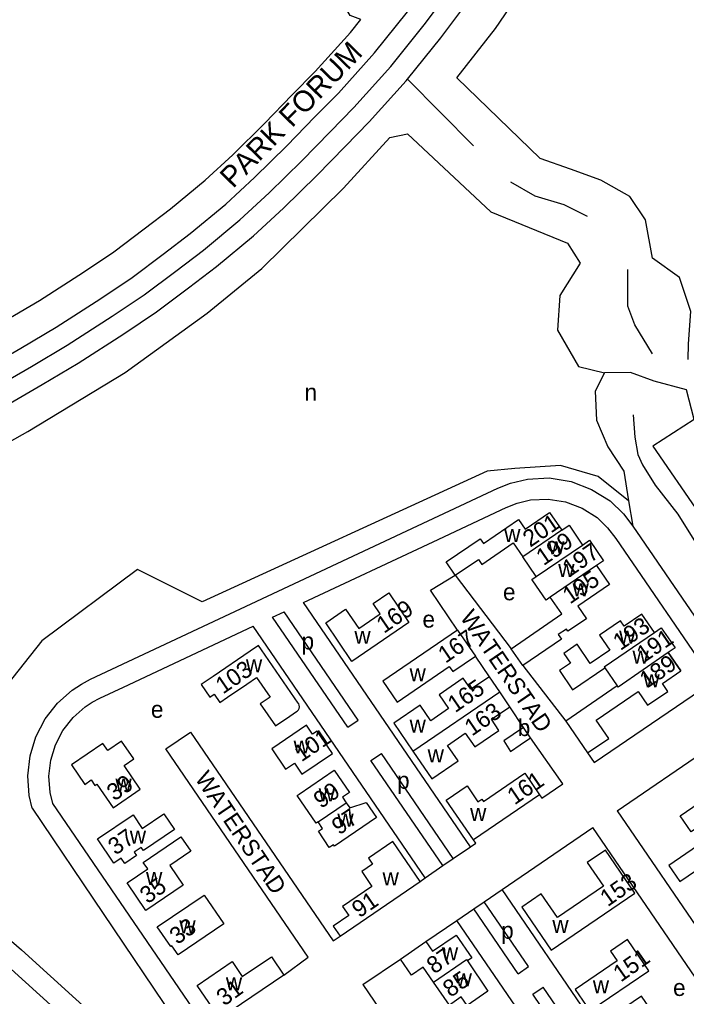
# Model space of a CAD drawing. Extents: x 154320 to 156262, y 382651 to 384180.
# Drawn here: x 155553.7 to 155711.8, y 383414.4 to 383646 of the extents above; entities that cross this region are included whole.
import ezdxf

# ---------------------------------------------------------------- set-up
doc = ezdxf.new("R2010")
doc.units = 0
for name, color, linetype in [('BLT_Basislijn', 7, 'Continuous'), ('BLT_Bebouwing', 7, 'Continuous'), ('BLT_Centroide', 7, 'Continuous'), ('BLT_Huisnummer', 7, 'Continuous'), ('BLT_Huisnummer_ tussenligend', 7, 'Continuous'), ('BLT_Onderverdeling_panden', 7, 'Continuous'), ('BLT_Straatnaam', 7, 'Continuous')]:
    doc.layers.add(name, color=color, linetype=linetype)

msp = doc.modelspace()

# ---------------------------------------------------------------- linework, layer by layer
at = {"layer": 'BLT_Basislijn'}
for p, q in [((155645.33, 383631.5), (155645.63, 383631.87)), ((155661.26, 383616.07), (155645.63, 383631.87)), ((155698.05, 383531.88), (155699.07, 383525.89)), ((155621, 383507.76), (155651.71, 383522.17)), ((155656.99, 383514.23), (155670.22, 383496.83)), ((155660.56, 383449.87), (155621, 383507.76)), ((155613.66, 383504.31), (155616.41, 383505.6)), ((155633.98, 383479.9), (155616.41, 383505.6)), ((155631.5, 383478.2), (155613.66, 383504.31)), ((155578.35, 383487.74), (155609.08, 383502.16)), ((155649.86, 383442.48), (155609.08, 383502.16)), ((155665.08, 383490.18), (155661.77, 383495.05)), ((155672.99, 383492.8), (155683.16, 383479.67)), ((155689.88, 383469.84), (155718.17, 383489.1)), ((155673.16, 383478.16), (155669.95, 383483.07)), ((155631.5, 383478.2), (155633.98, 383479.9)), ((155695.34, 383458.35), (155725.22, 383478.78)), ((155682.46, 383464.79), (155674.81, 383475.7)), ((155636.98, 383470.3), (155639.45, 383471.99)), ((155656.47, 383447.09), (155639.45, 383471.99)), ((155688.35, 383472.09), (155689.88, 383469.84)), ((155653.99, 383445.41), (155636.98, 383470.3)), ((155556.64, 383458.99), (155593.76, 383404.06)), ((155695.34, 383458.35), (155746.12, 383384.05)), ((155668.08, 383439.72), (155689.56, 383454.4)), ((155736.8, 383385.3), (155689.56, 383454.4)), ((155656.47, 383447.09), (155660.56, 383449.87)), ((155649.86, 383442.48), (155653.99, 383445.41)), ((155653.99, 383445.41), (155656.47, 383447.09)), ((155648.65, 383441.62), (155649.86, 383442.48)), ((155663.84, 383436.82), (155668.08, 383439.72)), ((155718.85, 383365.44), (155668.08, 383439.72)), ((155661.36, 383435.13), (155663.84, 383436.82)), ((155674.33, 383421.45), (155663.84, 383436.82)), ((155657.35, 383432.39), (155661.36, 383435.13)), ((155671.92, 383419.68), (155661.36, 383435.13)), ((155649.99, 383427.35), (155657.35, 383432.39)), ((155708.13, 383358.08), (155657.35, 383432.39)), ((155627.99, 383427.51), (155629.65, 383428.63)), ((155616.31, 383419.44), (155622.12, 383423.7)), ((155635.07, 383417.16), (155643.96, 383423.23)), ((155671.92, 383419.68), (155674.33, 383421.45)), ((155635.07, 383417.16), (155685.86, 383342.86)), ((155675.38, 383414.87), (155677.85, 383416.57)), ((155692.79, 383389.39), (155675.38, 383414.87)), ((155695.26, 383391.09), (155677.85, 383416.57))]:
    msp.add_line(p, q, dxfattribs=at)
for points in [[(155634.56, 383646.03), (155632.06, 383646.95), (155621.94, 383663.64), (155608.88, 383712.13), (155584.78, 383742.91), (155588.99, 383764.63), (155578.77, 383762.24), (155550.55, 383734.97), (155547.89, 383720.5), (155553.04, 383704.86), (155548.1, 383677.23), (155536.76, 383648.78), (155496.98, 383683.49), (155480.24, 383672.06), (155468.97, 383655.07), (155453.89, 383625.83), (155444.31, 383633.22), (155434.65, 383632.62), (155423.38, 383626.53), (155417.9, 383619.16), (155415.76, 383606.74), (155415.92, 383588.66), (155411.04, 383581.59)], [(155645.63, 383631.87), (155653.52, 383641.7), (155660.18, 383650.53), (155667.6, 383661.59), (155674.2, 383671.69), (155680.39, 383682.59), (155686.27, 383693.88), (155690.18, 383702.32), (155694.04, 383711.19), (155696.16, 383716.29)], [(155657.33, 383632.2), (155666.55, 383643.87), (155679.77, 383663.41), (155688.85, 383680.58), (155694.77, 383694.59), (155698.64, 383702.82)], [(155473.87, 383522.91), (155483.71, 383526.69), (155493.7, 383530.96), (155504.83, 383536.09), (155512.64, 383539.82), (155524.25, 383545.7), (155533.73, 383550.62), (155542.77, 383555.83), (155556.5, 383563.77), (155564.94, 383568.79), (155575.66, 383575.68), (155583.25, 383580.77), (155590.73, 383586.39), (155597.25, 383591.37), (155605.88, 383598.5), (155612.82, 383604.92), (155620.6, 383612.55), (155627.28, 383619.42), (155632.9, 383625.15), (155641.67, 383634.9), (155649.57, 383644.77), (155656.1, 383653.43)], [(155540.27, 383560.16), (155553.97, 383568.09), (155562.31, 383573.04), (155572.92, 383579.86), (155580.35, 383584.85), (155587.71, 383590.38), (155594.14, 383595.29), (155602.59, 383602.27), (155609.37, 383608.54), (155617.06, 383616.08), (155623.7, 383622.92), (155629.26, 383628.58), (155637.85, 383638.14), (155645.62, 383647.83)], [(155549, 383573.88), (155550.17, 383574.56), (155558.37, 383579.42), (155568.8, 383586.13), (155576, 383590.96), (155583.18, 383596.36), (155589.47, 383601.17), (155597.65, 383607.92), (155604.2, 383613.97), (155611.74, 383621.37), (155618.33, 383628.15), (155623.79, 383633.72), (155632.13, 383642.99), (155634.56, 383646.03)], [(155481.78, 383520.59), (155485.59, 383522.05), (155495.73, 383526.39), (155506.95, 383531.57), (155514.85, 383535.33), (155526.53, 383541.25), (155536.13, 383546.23), (155545.27, 383551.5), (155559.03, 383559.46), (155567.57, 383564.53), (155578.41, 383571.5), (155586.14, 383576.69), (155593.74, 383582.41), (155600.36, 383587.46), (155609.17, 383594.73), (155616.27, 383601.3), (155624.15, 383609.02), (155630.85, 383615.93), (155636.55, 383621.73), (155645.33, 383631.5)], [(155712.22, 383565.38), (155712.25, 383569.11), (155712.86, 383576.76), (155710.15, 383584.83), (155703.72, 383589.45), (155702.06, 383598.56), (155698.39, 383604.03), (155691.52, 383607.97), (155684.3, 383610.54), (155677.08, 383613.11), (155657.33, 383632.2)], [(155484.43, 383512.94), (155506.14, 383522.26), (155534.38, 383536.42), (155555.63, 383548.36), (155578.72, 383562.32), (155598.15, 383576.38), (155611.08, 383587.01), (155630.5, 383606.01), (155641.48, 383618.06), (155645.65, 383618.9)], [(155645.65, 383618.9), (155665.38, 383600.45), (155683.59, 383592.96), (155686.58, 383588.23), (155681.79, 383580.61), (155681.2, 383572.34), (155686.23, 383563.75), (155692.32, 383562.27)], [(155688.31, 383599.28), (155682.79, 383602.12), (155675.91, 383604.17), (155670.14, 383607.44)], [(155703.77, 383566.76), (155699.56, 383573.65), (155697.9, 383578.05), (155697.9, 383586.74)], [(155692.32, 383562.27), (155690.15, 383557.87), (155690.5, 383551.02), (155693.18, 383544.69), (155696.96, 383538.96), (155698.05, 383531.88)], [(155713.63, 383551.16), (155711.84, 383558.19), (155704.16, 383560.3), (155698.52, 383562.36), (155692.32, 383562.27)], [(155699.18, 383552.32), (155699.56, 383547.02), (155700.26, 383542.84), (155701.35, 383540.44), (155704.4, 383535.59), (155709.75, 383528.69), (155713.91, 383522), (155717.27, 383515.75), (155720.43, 383507.15), (155722.7, 383502.36), (155724.5, 383499.1)], [(155713.63, 383551.16), (155703.82, 383544.84), (155736.76, 383496.93)], [(155698.05, 383531.88), (155690.89, 383537.69), (155681.93, 383540.29), (155671.11, 383539.57), (155664.57, 383538.95), (155596.99, 383507.93), (155581.65, 383515.6), (155558.93, 383498.71), (155544.8, 383480.89), (155542.65, 383466.76)], [(155559.74, 383480.18), (155562.69, 383483.92), (155566.16, 383486.99), (155568.32, 383488.41), (155570.47, 383489.56), (155667.03, 383534.88), (155670.11, 383536.1), (155674.1, 383537.06), (155679.27, 383537.32), (155684.46, 383536.51), (155689.3, 383534.61), (155693.73, 383531.87), (155696.83, 383528.82), (155699.07, 383525.89)], [(155651.71, 383522.17), (155669.01, 383530.29), (155671.62, 383531.32), (155674.82, 383532.09), (155679.01, 383532.3), (155683.15, 383531.66), (155687.05, 383530.13), (155690.62, 383527.92), (155693.07, 383525.51), (155695.02, 383522.96), (155718.17, 383489.1)], [(155699.07, 383525.89), (155721.42, 383493.2)], [(155473.87, 383522.91), (155483.98, 383497.86), (155486.36, 383493.38), (155496.62, 383477.01), (155506.99, 383465.16), (155518.91, 383453.74), (155544.48, 383433.68), (155554.14, 383425.4), (155573.89, 383407.44), (155578.88, 383402.26), (155583.05, 383396.74)], [(155657.54, 383501.24), (155651.07, 383510.7), (155656.99, 383514.23)], [(155561.52, 383460.08), (155560.92, 383462.75), (155560.63, 383466.57), (155561.08, 383470.38), (155562.2, 383474.05), (155563.96, 383477.46), (155566.34, 383480.47), (155569.21, 383483.01), (155570.88, 383484.11), (155572.72, 383485.1), (155578.35, 383487.74)], [(155556.64, 383458.99), (155555.96, 383462.01), (155555.61, 383466.68), (155556.17, 383471.41), (155557.55, 383475.94), (155559.74, 383480.18)], [(155588.38, 383473.06), (155594.16, 383477.01), (155627.99, 383427.51)], [(155622.12, 383423.7), (155588.38, 383473.06)], [(155676.94, 383462.17), (155677.47, 383461.39), (155682.46, 383464.79)], [(155597.88, 383406.88), (155561.52, 383460.08)], [(155660.56, 383449.87), (155661.82, 383450.73), (155661.29, 383451.5)], [(155541.74, 383429.44), (155550.83, 383421.65), (155570.4, 383403.86), (155575.07, 383399.01), (155578.92, 383393.92)]]:
    msp.add_lwpolyline(points, dxfattribs=at)
at = {"layer": 'BLT_Bebouwing'}
for p, q in [((155676.18, 383513.95), (155673, 383518.59)), ((155657.54, 383501.24), (155661.77, 383495.05)), ((155610.34, 383497.6), (155608.35, 383496.24)), ((155672.99, 383492.8), (155670.22, 383496.83)), ((155707.48, 383495.9), (155710.43, 383491.56)), ((155692.46, 383492.29), (155695.37, 383488.03)), ((155667.52, 383486.62), (155665.08, 383490.18)), ((155669.95, 383483.07), (155667.52, 383486.62)), ((155695.37, 383488.03), (155683.16, 383479.67)), ((155683.16, 383479.67), (155688.35, 383472.09)), ((155676.94, 383462.17), (155661.29, 383451.5)), ((155629.65, 383428.63), (155648.65, 383441.62)), ((155643.96, 383423.23), (155649.99, 383427.35)), ((155616.31, 383419.44), (155601.13, 383409.09))]:
    msp.add_line(p, q, dxfattribs=at)
for points in [[(155656.99, 383514.23), (155654.82, 383517.4), (155662.86, 383522.88), (155663.65, 383521.74), (155671.99, 383527.44), (155673.51, 383525.2), (155679.32, 383529.16), (155682.23, 383524.9)], [(155682.23, 383524.9), (155683.96, 383526.12), (155687.16, 383521.41)], [(155656.99, 383514.23), (155662.45, 383517.95), (155663.24, 383516.8), (155670.72, 383521.92), (155673, 383518.59)], [(155687.16, 383521.41), (155688.83, 383522.53), (155692.15, 383517.66), (155690.49, 383516.54)], [(155690.49, 383516.54), (155693.56, 383512.06), (155686.02, 383506.91), (155688.08, 383503.89), (155683.65, 383500.97), (155683.32, 383501.47), (155681.41, 383500.21), (155682.2, 383499.07), (155672.99, 383492.8)], [(155679.51, 383509.07), (155678.49, 383508.37), (155675.38, 383512.89), (155675.14, 383513.23), (155676.18, 383513.95)], [(155670.22, 383496.83), (155682.25, 383505.08), (155679.51, 383509.07)], [(155704.19, 383500.69), (155701.23, 383505), (155697.04, 383502.14), (155696.12, 383503.46), (155691.18, 383500.07), (155693.64, 383496.48), (155688.99, 383493.32), (155685.89, 383497.86), (155682.73, 383495.7), (155684.29, 383493.41), (155681.66, 383491.63), (155684.79, 383487.04), (155692.46, 383492.29)], [(155657.54, 383501.24), (155639.79, 383489.11), (155643.18, 383484.16), (155655.56, 383492.62), (155656.41, 383491.38), (155661.77, 383495.05)], [(155704.19, 383500.69), (155705.83, 383501.8), (155709.09, 383497.06), (155707.48, 383495.9)], [(155608.35, 383496.24), (155599.59, 383490.27), (155596.71, 383488.3), (155598.75, 383485.34), (155599.79, 383486.05), (155601.15, 383484.07), (155602.97, 383485.3), (155607.54, 383488.42), (155609.88, 383490.01), (155613.07, 383485.34), (155610.75, 383483.75), (155614.33, 383478.53), (155617.74, 383480.84)], [(155619.73, 383483.91), (155611.07, 383496.53), (155610.34, 383497.6)], [(155688.35, 383472.09), (155693.38, 383475.54), (155690.42, 383479.86), (155700.36, 383486.65), (155702.56, 383483.42), (155707.38, 383486.71), (155706.12, 383488.6), (155710.43, 383491.56), (155707.48, 383495.9)], [(155665.08, 383490.18), (155660.65, 383487.25), (155658.87, 383489.81), (155653.17, 383485.91), (155655.38, 383482.62), (155651.15, 383479.73), (155648.63, 383483.43), (155642.38, 383479.15), (155646.88, 383472.55)], [(155617.74, 383480.84), (155619.32, 383481.9), (155619.56, 383482.08), (155619.77, 383482.32), (155619.94, 383482.65), (155620.02, 383483.05), (155619.97, 383483.45), (155619.85, 383483.73), (155619.73, 383483.91)], [(155646.88, 383472.55), (155651.38, 383465.95), (155657.66, 383470.23), (155655.16, 383473.9), (155659.36, 383476.8), (155661.59, 383473.52), (155667.34, 383477.44), (155665.55, 383480.08), (155669.95, 383483.07)], [(155673.16, 383478.16), (155670.69, 383476.49), (155668.46, 383474.94), (155670.07, 383472.48), (155672.35, 383474.04), (155674.81, 383475.7)], [(155674.81, 383475.7), (155673.16, 383478.16)], [(155624.49, 383455.77), (155623.97, 383455.41), (155619.46, 383462.01), (155620, 383462.35), (155628.26, 383468), (155631.88, 383462.7), (155630.26, 383461.59), (155631.12, 383460.3)], [(155661.29, 383451.5), (155654.85, 383460.94), (155659.76, 383464.29), (155662.35, 383460.5), (155663.27, 383461.13), (155663.65, 383460.58), (155673.47, 383467.27), (155676.94, 383462.17)], [(155631.12, 383460.3), (155631.96, 383459.08), (155635.84, 383460.34), (155638.29, 383456.76), (155628.35, 383449.98), (155628.1, 383450.35), (155627.11, 383449.69), (155624.51, 383453.55), (155625.5, 383454.22), (155624.49, 383455.77)], [(155648.65, 383441.62), (155642.2, 383451.07), (155636.43, 383447.11), (155637.39, 383445.72), (155634.81, 383443.96), (155637.21, 383440.45), (155630.27, 383435.71), (155631.75, 383433.53), (155628.03, 383430.99), (155629.65, 383428.63)], [(155649.99, 383427.35), (155651.54, 383425.08), (155657.2, 383428.87), (155660.87, 383423.49), (155659.87, 383422.81)], [(155601.13, 383409.09), (155595.78, 383416.98), (155604.04, 383422.64), (155606.48, 383419.06), (155613.38, 383423.78), (155616.31, 383419.44)], [(155651.85, 383417.77), (155649.4, 383421.33), (155646.57, 383419.42), (155643.96, 383423.23)], [(155659.87, 383422.81), (155664.73, 383415.61), (155659.79, 383412.24), (155658.41, 383414.23), (155655.62, 383412.27), (155651.85, 383417.77)]]:
    msp.add_lwpolyline(points, dxfattribs=at)
for points in [[(155641.2, 383510.08), (155646, 383503.05), (155632.47, 383493.78), (155626.26, 383502.99), (155630.94, 383506.2), (155634.13, 383501.63), (155639.17, 383505.08), (155637.49, 383507.54)], [(155621.69, 383478.68), (155613.46, 383473.06), (155616.73, 383468.27), (155618.82, 383469.7), (155620.62, 383467.05), (155627.86, 383472), (155624.25, 383477.29), (155623.15, 383476.54)], [(155578.45, 383469.11), (155580.73, 383470.67), (155577.83, 383474.92), (155574.56, 383472.68), (155573.39, 383474.37), (155565.96, 383469.25), (155569.14, 383464.65), (155570.65, 383465.7), (155571.55, 383464.36), (155572.02, 383464.68), (155575.87, 383459.08), (155582.29, 383463.49)], [(155722.74, 383473.61), (155727.9, 383466.08), (155725.81, 383464.65), (155726.93, 383463.03), (155712.87, 383453.41), (155710.28, 383457.21), (155717.54, 383462.18), (155714.43, 383466.72), (155714.97, 383467.09), (155714.41, 383467.91)], [(155730.98, 383461.43), (155707.64, 383445.38), (155710.25, 383441.58), (155722.07, 383449.69), (155724.14, 383446.67), (155735.68, 383454.59)], [(155572.14, 383451.7), (155580.58, 383457.42), (155582.72, 383454.19), (155587.85, 383457.67), (155590.38, 383453.95), (155583.05, 383448.94), (155582.53, 383449.7), (155580.87, 383448.55), (155581.39, 383447.79), (155578.6, 383445.9), (155577.73, 383447.17), (155576, 383446)], [(155591.92, 383452.24), (155594.27, 383448.8), (155589.27, 383445.39), (155592.44, 383440.72), (155583.64, 383434.71), (155579.17, 383441.26), (155584.05, 383444.6), (155583, 383446.13)], [(155692.58, 383449.07), (155688.27, 383446.12), (155692.1, 383440.52), (155681.21, 383433.05), (155677.37, 383438.68), (155672.74, 383435.52), (155679.74, 383425.32), (155699.59, 383438.85)], [(155602.09, 383431.57), (155591.28, 383424.19), (155589.81, 383426.36), (155589.53, 383426.17), (155586.33, 383430.9), (155597.43, 383438.41)], [(155697.78, 383427.86), (155693.81, 383425.08), (155695.35, 383422.82), (155685.43, 383416.04), (155688.91, 383410.93), (155702.86, 383420.43)], [(155705.07, 383408.64), (155701.13, 383414.42), (155691.22, 383407.67), (155695.17, 383401.89)]]:
    msp.add_lwpolyline(points, close=True, dxfattribs=at)
at = {"layer": 'BLT_Onderverdeling_panden'}
for p, q in [((155682.23, 383524.9), (155673, 383518.59)), ((155676.18, 383513.95), (155687.16, 383521.41)), ((155690.49, 383516.54), (155679.51, 383509.07)), ((155692.28, 383492.54), (155704.19, 383500.69)), ((155692.28, 383492.54), (155692.46, 383492.29)), ((155646.88, 383472.55), (155667.52, 383486.62)), ((155624.49, 383455.77), (155631.12, 383460.3))]:
    msp.add_line(p, q, dxfattribs=at)
for points in [[(155707.48, 383495.9), (155695.57, 383487.74), (155695.37, 383488.03)], [(155651.85, 383417.77), (155659.67, 383423.1), (155659.87, 383422.81)]]:
    msp.add_lwpolyline(points, dxfattribs=at)

# ---------------------------------------------------------------- texts
at = {"layer": 'BLT_Centroide'}
for s, p in [('n', (155621.24, 383555.63)), ('w', (155668.57, 383522.11)), ('w', (155679, 383519.18)), ('w', (155681.39, 383513.81)), ('w', (155684.79, 383509.28)), ('e', (155668.29, 383508.3)), ('e', (155649.2, 383501.82)), ('w', (155633.06, 383497.98)), ('w', (155695.83, 383498.01)), ('p', (155620.53, 383496.63)), ('w', (155698.99, 383493.3)), ('w', (155607.34, 383491.22)), ('w', (155646.14, 383489.12)), ('w', (155701.6, 383487.69)), ('e', (155584.82, 383480.44)), ('w', (155646.14, 383476.93)), ('b', (155671.79, 383476.1)), ('w', (155618.63, 383471.98)), ('w', (155650.42, 383469.85)), ('w', (155576.4, 383462.94)), ('p', (155643.17, 383463.61)), ('w', (155624.59, 383460.62)), ('w', (155660.49, 383455.97)), ('w', (155629.02, 383454.65)), ('w', (155579.8, 383450.62)), ('w', (155583.66, 383440.78)), ('w', (155639.73, 383440.69)), ('w', (155591.55, 383429.31)), ('p', (155667.85, 383428.02)), ('w', (155679.99, 383429.44)), ('w', (155653.79, 383422.9)), ('w', (155657.06, 383416.74)), ('w', (155602.59, 383415.81)), ('w', (155689.59, 383415.12)), ('e', (155708.62, 383414.47))]:
    msp.add_text(s, height=4, dxfattribs=at).set_placement(p)
at = {"layer": 'BLT_Huisnummer'}
for s, rotation, p in [('201', 34.4, (155674.75, 383520.75)), ('199', 34.4, (155677.91, 383516.39)), ('195', 34.4, (155684.18, 383507.29)), ('169', 34.4, (155640.06, 383500.32)), ('193', 34.4, (155696.12, 383496.26)), ('167', 34.4, (155654.66, 383493.24)), ('103', 34.4, (155601.9, 383485.94)), ('189', 34.4, (155702.45, 383487.32)), ('165', 34.4, (155656.94, 383481.51)), ('163', 34.4, (155660.93, 383475.97)), ('101', 34.4, (155620.51, 383469.85)), ('39', 34.3542, (155576.12, 383460.56)), ('161', 34.4, (155671.05, 383459.65)), ('99', 34.4, (155625.13, 383458.78)), ('97', 34.4, (155629.44, 383452.51)), ('37', 34.3534, (155576.4, 383447.72)), ('35', 35.8967, (155584.05, 383436.18)), ('153', 35.0638, (155693.12, 383435.51)), ('91', 34.4, (155634.21, 383432.86)), ('33', 35.8967, (155591.09, 383426.51)), ('87', 35.0638, (155651.98, 383419.54)), ('151', 35.0638, (155696.22, 383417.63)), ('85', 35.0638, (155655.83, 383414)), ('31', 35.8967, (155602.2, 383411.94))]:
    msp.add_text(s, height=4, rotation=rotation, dxfattribs=at).set_placement(p)
at = {"layer": 'BLT_Huisnummer_ tussenligend'}
for s, p in [('197', (155684.14, 383513.77)), ('191', (155701.72, 383493.4))]:
    msp.add_text(s, height=4, rotation=34.4, dxfattribs=at).set_placement(p)
at = {"layer": 'BLT_Straatnaam'}
for s, height, rotation, p in [('PARK FORUM', 5, 45.8551, (155604.28, 383605.8)), ('WATERSTAD', 4, 304.3967, (155657.96, 383504.27)), ('WATERSTAD', 4, 303.8967, (155595.11, 383466.06))]:
    msp.add_text(s, height=height, rotation=rotation, dxfattribs=at).set_placement(p)

doc.saveas('drawing.dxf')
